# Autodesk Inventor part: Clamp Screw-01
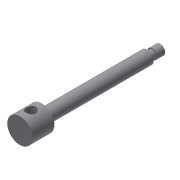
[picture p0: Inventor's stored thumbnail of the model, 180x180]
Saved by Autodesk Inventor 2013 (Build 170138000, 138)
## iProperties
Shininess: 77.0
Length Units: 11269
Angle Units: 11279
Time Units: 11290
Mass Units: 11283
Length Display Precision: 3
Angle Display Precision: 2
Created: 2002-02
Part Number: Clamp Screw-01
Document SubType Name: Modeling
Designer: ***
Density: 1 g/cm^3
Material: Generic
Density: 0.0
Volumn: 0.0
Area: 0.0
PropertySet Name: Model Information
Control State: 0
Master: False
Checked Out: False
Author: ***
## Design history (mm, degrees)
sketch "Sketch1"
  geometry: L1 (0, 140)-(5, 140); L2 (5, 140)-(5, 132); L3 (5, 132)-(4, 132); L4 (4, 132)-(4, 127); L5 (4, 127)-(22.5, 127); L6 (22.5, 127)-(22.5, 25); L7 (22.5, 25)-(21, 25); L8 (21, 25)-(21, 22); L9 (21, 22)-(12.5, 22); L10 (12.5, 22)-(12.5, 0); L11 (12.5, 0)-(0, 0); L12 (0, 0)-(0, 140)
  constraints: 24 end point, 10 parallel, 1 horizontal, 1 perpendicular
  dimensions: "d0" = 10 diameter of L2 L12; "d1" = 8 diameter of L4 L12; "d2" = 45 diameter of L6 L12; "d3" = 42 diameter of L7.end L12; "d4" = 25 diameter of L10 L12; "d5" = 3 distance from line of L7.end L9; "d6" = 8 distance of L1.end L2.end; "d7" = 13 vertical distance of L1.end L5.end; "d8" = 22 distance of L9.end L10.end; "d10" = 102 distance of L5.end L6.end
revolve "Revolution1" sketch "Sketch1" stored, may be unused: angle "d11" = 90 deg
sketch "Sketch3"
  geometry: L1 (-12.5, 0)-(12.5, 0) reference; C1 r 5 at (-0.113, 11)
  constraints: 1 centre point
  dimensions: "d13" = 10 diameter of C1; "d14" = 11 distance from line of L1 C1.centre
extrude "Extrusion1" cut sketch "Sketch3" stored distance "d15" = 10; taper "d16" = 0 deg
body "Solid1"
